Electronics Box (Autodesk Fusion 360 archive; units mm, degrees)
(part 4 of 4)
sketch "Sketch1" plane through (0, 0, 0) normal (0, 0, 1) x axis (1, 0, 0)
  line L1 (-9.075, -31) -> (9.075, -31)
  line L2 (-9.075, 31) -> (-9.075, -31)
  line L3 (9.075, 31) -> (-9.075, 31)
  line L4 (9.075, -31) -> (9.075, 31)
  line L5 (-9.075, 31) -> (9.075, -31)
  line L6 (9.075, 31) -> (-9.075, -31)
  line L7 (0, -31) -> (0, 31)
  line L8 (-3.75, 26) -> (3.75, 26)
  line L9 (-3.75, 31.7) -> (-3.75, 26)
  line L10 (3.75, 31.7) -> (-3.75, 31.7)
  line L11 (3.75, 26) -> (3.75, 31.7)
  line L12 (-3.75, 31.7) -> (3.75, 26)
  line L13 (3.75, 31.7) -> (-3.75, 26)
  line L14 (6.575, 31) -> (9.075, 31)
  line L15 (6.575, -31) -> (6.575, 31)
  line L16 (9.075, -31) -> (6.575, -31)
  line L17 (9.075, 31) -> (9.075, -31)
  line L18 (-6.575, 31) -> (-9.075, 31)
  line L19 (-6.575, -31) -> (-6.575, 31)
  line L20 (-9.075, -31) -> (-6.575, -31)
  line L21 (-9.075, 31) -> (-9.075, -31)
  point P6 (0, 0)
  point P1 (0, 0)
  point P7 (0, 31)
  point P8 (0, -31)
  point P13 (0, 28.85)
  point P15 (6.575, -31)
  point P18 (-6.575, -31)
  point P4 (-9.075, 31)
  point P5 (9.075, 31)
  point P2 (9.075, -31)
  point P9 (3.75, 26)
  point P10 (-3.75, 26)
  horizontal L1
  perpendicular L1 L2
  parallel L1 L3
  parallel L2 L4
  coincident L5 P6
  coincident L6 P6
  coincident P1 P6
  midpoint L3 P7
  midpoint L1 P8
  horizontal L8
  perpendicular L8 L9
  parallel L8 L10
  parallel L9 L11
  coincident L12 P13
  coincident L13 P13
  coincident L7 P13
  horizontal L14
  vertical L15
  horizontal L16
  vertical L17
  coincident L1 P15
  horizontal L18
  vertical L19
  horizontal L20
  vertical L21
  coincident L1 P18
  dimension "d1" distance P4 P5 = 18.15
  dimension "d2" distance P2 P5 = 62
  dimension "d3" distance L3 L10 = 0.7
  dimension "d4" distance L8 L10 = 5.7
  dimension "d5" distance P9 P10 = 7.5
  dimension "d6" distance L19 L21 = 2.5
  dimension "d7" distance L4 L15 = 2.5
extrude "Extrude1" new body sketch "Sketch1" profile of L1 L2 L3 L4 L8 L9 L11 L14 L15 L16 L17 L18 L19 L20 L21 along normal blind 3
extrude "Extrude2" new body sketch "Sketch1" profile of L1 L2 L3 L4 L14 L15 L16 L17 L18 L19 L20 L21 against normal blind 11
extrude "Extrude3" sketch "Sketch1" profile of L3 L8 L9 L10 L11 blind 3.07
